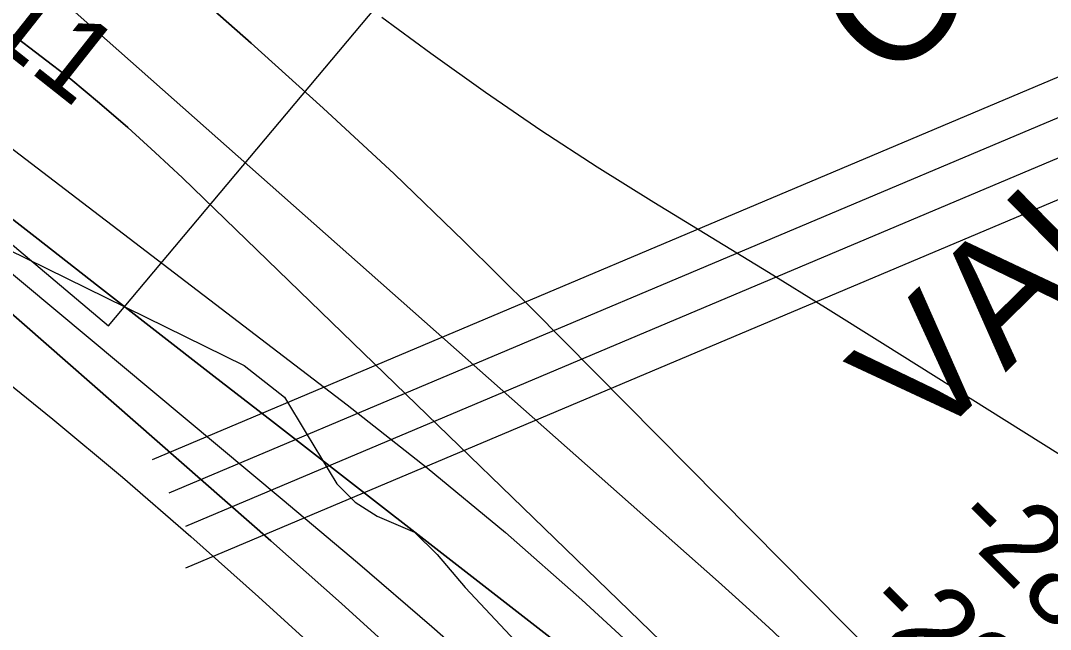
# Model space of a CAD drawing. Extents: x 3568792 to 3606828, y 529143 to 554785.
# Drawn here: x 3573791 to 3574634, y 541123 to 541622 of the extents above; entities that cross this region are included whole.
import ezdxf

# ---------------------------------------------------------------- set-up
doc = ezdxf.new("R2010")
doc.units = 0
for name, color, linetype in [('V-CHAN-NAID', 7, 'Continuous'), ('V-RIVR-EDGE', 7, 'Continuous'), ('V-RIVR-IDEN', 7, 'Continuous'), ('V-RIVR-RANG', 7, 'Continuous'), ('V-RRAP-RVMT', 7, 'Continuous'), ('V-TOPO-DPTH', 7, 'Continuous'), ('V-TOPO-MINR', 7, 'Continuous'), ('V-TOPO-WATR', 7, 'Continuous'), ('V-UTIL-LINE', 7, 'Continuous')]:
    doc.layers.add(name, color=color, linetype=linetype)

msp = doc.modelspace()

# ---------------------------------------------------------------- linework, layer by layer
at = {"layer": 'V-RIVR-EDGE'}
msp.add_lwpolyline([(3573780.38, 541434.56), (3573974.05, 541339.22), (3574007.01, 541313.33), (3574024.94, 541283.87), (3574050.05, 541242.38), (3574065.03, 541227.34), (3574083.01, 541215.89), (3574113.59, 541202.61), (3574132.16, 541184.55), (3574154.9, 541157.48), (3574192.02, 541117.77), (3574242.92, 541063.01), (3574278.86, 541032.3), (3574389.61, 540904.76), (3574426.07, 540841.64), (3574512.1, 540673.33), (3574548.66, 540647.43), (3574603.76, 540597.47), (3574652.27, 540549.92), (3574690.57, 540498.8)], dxfattribs=at)
at = {"layer": 'V-RRAP-RVMT'}
for p, q in [((3573862.98, 541371.7), (3574157.04, 541722.43)), ((3573762.24, 541456.65), (3573862.98, 541371.7))]:
    msp.add_line(p, q, dxfattribs=at)
at = {"layer": 'V-TOPO-DPTH'}
for points in [[(3573787.37, 541759.74), (3573800.88, 541751.64), (3573814, 541742.92), (3573826.84, 541733.77), (3573855.94, 541711.97), (3573858.41, 541710.07), (3573860.85, 541708.13), (3573863.25, 541706.13), (3573865.61, 541704.09), (3573979.8, 541603.16), (3574038.68, 541550.04), (3574096.85, 541496.16), (3574153.92, 541441.13), (3574210.26, 541385.33), (3574491.42, 541101.26), (3574507.94, 541084.15), (3574524.16, 541066.78), (3574539.95, 541049.01), (3574555.44, 541030.98), (3575073.88, 540412.24)], [(3575073.88, 540412.24), (3574555.44, 541030.98), (3574539.95, 541049.01), (3574524.16, 541066.78), (3574507.94, 541084.15), (3574491.42, 541101.26), (3574210.26, 541385.33), (3574153.92, 541441.13), (3574096.85, 541496.16), (3574038.68, 541550.04), (3573979.8, 541603.16), (3573865.61, 541704.09), (3573863.25, 541706.13), (3573860.85, 541708.13), (3573858.41, 541710.07), (3573855.94, 541711.97), (3573826.84, 541733.77), (3573814, 541742.92), (3573800.88, 541751.64), (3573787.37, 541759.74)], [(3574086.78, 541624.62), (3574126.95, 541595.03), (3574171.64, 541563.05), (3574216.89, 541531.89), (3574262.97, 541501.98), (3574309.6, 541472.89), (3574356.58, 541444.32), (3574403.47, 541415.59), (3574450.21, 541386.64), (3574496.87, 541357.53), (3574670.41, 541248.65)], [(3574086.78, 541624.62), (3574126.95, 541595.03), (3574171.64, 541563.05), (3574216.89, 541531.89), (3574262.97, 541501.98), (3574309.6, 541472.89), (3574356.58, 541444.32), (3574403.47, 541415.59), (3574450.21, 541386.64), (3574496.87, 541357.53), (3574670.41, 541248.65)], [(3574820.32, 540517.41), (3574794.33, 540554.08), (3574767.75, 540590.3), (3574740.3, 540625.87), (3574712.26, 540661), (3574466.89, 540960.89), (3574455.69, 540974.1), (3574444.2, 540987.04), (3574432.27, 540999.57), (3574420.04, 541011.83), (3573923.49, 541492.84), (3573901.27, 541513.78), (3573878.67, 541534.29), (3573855.52, 541554.17), (3573831.99, 541573.62), (3573807.95, 541592.45), (3573783.61, 541610.87)], [(3573783.61, 541610.87), (3573807.95, 541592.45), (3573831.99, 541573.62), (3573855.52, 541554.17), (3573878.67, 541534.29), (3573901.27, 541513.78), (3573923.49, 541492.84), (3574420.04, 541011.83), (3574432.27, 540999.57), (3574444.2, 540987.04), (3574455.69, 540974.1), (3574466.89, 540960.89), (3574712.26, 540661), (3574740.3, 540625.87), (3574767.75, 540590.3), (3574794.33, 540554.08), (3574820.32, 540517.41)], [(3575499.11, 539427.66), (3574585.6, 540708.28), (3574423.67, 540959.29), (3574423.2, 540960), (3574421.66, 540962.09), (3574420.48, 540963.53), (3574417.75, 540966.1), (3574415.79, 540967.79), (3574411.98, 540970.75), (3574409.55, 540972.62), (3574407.13, 540974.5), (3574404.71, 540976.37), (3574402.29, 540978.25), (3573997.25, 541293.29), (3573949.25, 541330.63), (3573901.24, 541367.98), (3573853.24, 541405.33), (3573805.24, 541442.68), (3573758.52, 541479.03)], [(3573758.52, 541479.03), (3573805.24, 541442.68), (3573853.24, 541405.33), (3573901.24, 541367.98), (3573949.25, 541330.63), (3573997.25, 541293.29), (3574402.29, 540978.25), (3574404.71, 540976.37), (3574407.13, 540974.5), (3574409.55, 540972.62), (3574411.98, 540970.75), (3574415.79, 540967.79), (3574417.75, 540966.1), (3574420.48, 540963.53), (3574421.66, 540962.09), (3574423.2, 540960), (3574423.67, 540959.29), (3574585.6, 540708.28), (3574628.75, 540647.8)], [(3574628.75, 540647.8), (3574261.07, 540720.58), (3574264.37, 540720.59), (3574271.23, 540720.81), (3574278.08, 540721.18), (3574337.74, 540725.3), (3574360.89, 540735.41), (3574376.45, 540749.79), (3574380.62, 540770.57), (3574377.19, 540795.61), (3574370.89, 540807.74), (3574351.19, 540841.55), (3574329.49, 540873.87), (3574304.79, 540903.96), (3574278.09, 540932.57), (3574223.54, 540985.62), (3574167.62, 541039.17), (3574111.15, 541092.12), (3574053.85, 541144.17), (3573996.01, 541195.63), (3573683.04, 541469.63)]]:
    msp.add_lwpolyline(points, dxfattribs=at)
at = {"layer": 'V-TOPO-MINR'}
for points in [[(3573787.37, 541759.74), (3573800.88, 541751.64), (3573814, 541742.92), (3573826.84, 541733.77), (3573855.94, 541711.97), (3573858.41, 541710.07), (3573860.85, 541708.13), (3573863.25, 541706.13), (3573865.61, 541704.09), (3573979.8, 541603.16), (3574038.68, 541550.04), (3574096.85, 541496.16), (3574153.92, 541441.13), (3574210.26, 541385.33), (3574491.42, 541101.26), (3574507.94, 541084.15), (3574524.16, 541066.78), (3574539.95, 541049.01), (3574555.44, 541030.98), (3575073.88, 540412.24)], [(3573789.05, 541665.46), (3573801.03, 541656.69), (3573812.8, 541647.67), (3573824.27, 541638.27), (3573835.54, 541628.61), (3574362.38, 541162.12), (3574384.9, 541141.82), (3574407.17, 541121.27), (3574429.07, 541100.33), (3574450.74, 541079.13), (3574491.2, 541038.82), (3574493.64, 541036.28), (3574495.96, 541033.64), (3574516.06, 541009.78), (3574527.07, 540996.37), (3574537.84, 540982.77), (3574548.26, 540968.9), (3574558.44, 540954.85), (3574599.98, 540895.94), (3574630.79, 540852.32), (3574661.64, 540808.73), (3574692.56, 540765.19), (3574723.53, 540721.69), (3574957.39, 540393.71)], [(3574086.78, 541624.62), (3574126.95, 541595.03), (3574171.64, 541563.05), (3574216.89, 541531.89), (3574262.97, 541501.98), (3574309.6, 541472.89), (3574356.58, 541444.32), (3574403.47, 541415.59), (3574450.21, 541386.64), (3574496.87, 541357.53), (3574670.41, 541248.65)], [(3573783.61, 541610.87), (3573807.95, 541592.45), (3573831.99, 541573.62), (3573855.52, 541554.17), (3573878.67, 541534.29), (3573901.27, 541513.78), (3573923.49, 541492.84), (3574420.04, 541011.83), (3574432.27, 540999.57), (3574444.2, 540987.04), (3574455.69, 540974.1), (3574466.89, 540960.89), (3574712.26, 540661), (3574740.3, 540625.87), (3574767.75, 540590.3), (3574794.33, 540554.08), (3574820.32, 540517.41)], [(3573742.77, 541548.03), (3574058.46, 541307.06), (3574123.9, 541255.39), (3574188.15, 541202.33), (3574250.64, 541147.2), (3574311.94, 541090.69), (3574420.11, 540987.62), (3574426.31, 540981.49), (3574432.35, 540975.19), (3574438.14, 540968.68), (3574443.76, 540962.01), (3574509.01, 540881.53), (3574546.49, 540834.04), (3574583.11, 540785.91), (3574618.44, 540736.82), (3574652.92, 540687.1), (3574722.15, 540584.4), (3574731.45, 540569.2), (3575324.87, 539720.09)], [(3573713.54, 541472.91), (3574005.23, 541229.71), (3574066.75, 541177.81), (3574127.85, 541125.43), (3574188.33, 541072.34), (3574248.4, 541018.77), (3574348.69, 540928.28), (3574358.11, 540919.41), (3574367.28, 540910.3), (3574376.06, 540900.81), (3574384.59, 540891.07), (3574424.88, 540843.08), (3574446.44, 540814.59), (3574465.94, 540784.9), (3574482.35, 540753.39), (3574496.7, 540720.67), (3574500.62, 540710.33)], [(3573683.04, 541469.63), (3573996.01, 541195.63), (3574053.85, 541144.17), (3574111.15, 541092.12), (3574167.62, 541039.17), (3574223.54, 540985.62), (3574278.09, 540932.57), (3574304.79, 540903.96), (3574329.49, 540873.87), (3574351.19, 540841.55), (3574370.89, 540807.74), (3574377.19, 540795.61), (3574380.62, 540770.57), (3574376.45, 540749.79), (3574360.89, 540735.41), (3574337.74, 540725.3), (3574278.08, 540721.18), (3574271.23, 540720.81), (3574264.37, 540720.59), (3574261.07, 540720.58)], [(3573759.44, 541341.86), (3573817.25, 541295.28), (3573874.38, 541247.89), (3573930.48, 541199.3), (3573985.89, 541149.9), (3574277.36, 540884.44), (3574293.25, 540868.53), (3574308.03, 540851.73), (3574321.15, 540833.61), (3574333.17, 540814.61), (3574336.16, 540809.34), (3574337.18, 540796.54), (3574334.27, 540786.95), (3574325.45, 540782.18), (3574312.7, 540780.62), (3574286.64, 540789.12), (3574271.64, 540794.89), (3574257.17, 540801.63), (3574243.48, 540809.84), (3574230.31, 540819.04), (3574196.93, 540845.01)]]:
    msp.add_lwpolyline(points, dxfattribs=at)
at = {"layer": 'V-TOPO-WATR'}
msp.add_lwpolyline([(3573758.52, 541479.03), (3573805.24, 541442.68), (3573853.24, 541405.33), (3573901.24, 541367.98), (3573949.25, 541330.63), (3573997.25, 541293.29), (3574402.29, 540978.25), (3574404.71, 540976.37), (3574407.13, 540974.5), (3574409.55, 540972.62), (3574411.98, 540970.75), (3574415.79, 540967.79), (3574417.75, 540966.1), (3574420.48, 540963.53), (3574421.66, 540962.09), (3574423.2, 540960), (3574423.67, 540959.29), (3574585.6, 540708.28), (3575499.11, 539427.66)], dxfattribs=at)
at = {"layer": 'V-UTIL-LINE'}
for p, q in [((3576409.25, 542322.42), (3573898.69, 541262.09)), ((3576422.93, 542295.05), (3573912.37, 541234.73)), ((3576436.61, 542267.69), (3573926.05, 541207.37)), ((3576436.61, 542233.48), (3573926.05, 541173.17))]:
    msp.add_line(p, q, dxfattribs=at)

# ---------------------------------------------------------------- texts
at = {"layer": 'V-CHAN-NAID'}
msp.add_text('VALERO NO. 2 (125.4) (2)', height=100, rotation=44.43645, dxfattribs=at).set_placement((3574533.66, 541270.88))
at = {"layer": 'V-RIVR-IDEN'}
msp.add_text('GOOD HOPE LDG.', height=99.9998, rotation=44.69029, dxfattribs=at).set_placement((3574503.57, 541566.95))
at = {"layer": 'V-RIVR-RANG'}
for s, rotation, p in [('-11', 321.6615, (3573734.32, 541630.19)), ('-28', 315.06325, (3574551.08, 541209.31)), ('-22', 315.06325, (3574478.78, 541140.18))]:
    msp.add_text(s, height=67, rotation=rotation, dxfattribs=at).set_placement(p)

doc.saveas('drawing.dxf')
